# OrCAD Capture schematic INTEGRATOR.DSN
size A; title: Integrator; rev: A; company: EMA Design Automation; note: EMA-12345678; note: 225 Tech Park Dr; note: Rochester, NY, 14623
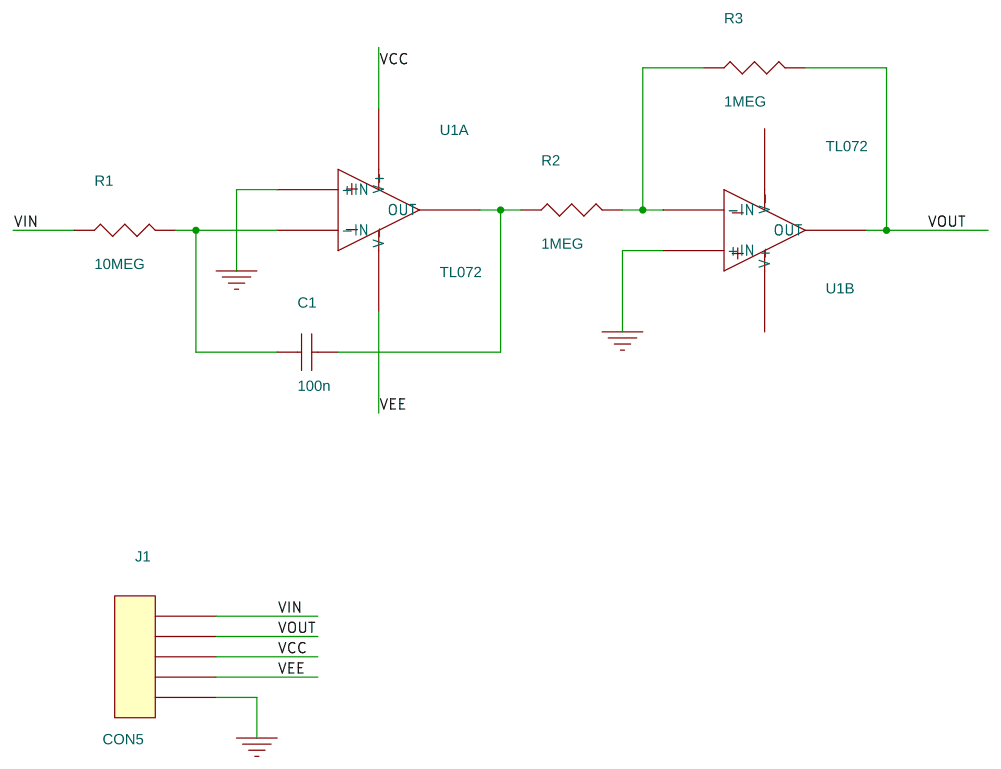
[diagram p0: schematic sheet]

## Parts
C1  100n
J1  CON5
R1  10MEG
R2  1MEG
R3  1MEG
U1  TL072  (sections A,B)

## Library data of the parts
C1 = CAP_NP
J1 = CON5
R1-R3 = RESISTOR
U1 = TL072_0

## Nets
GND: J1.5 U1.3(+IN) U1.5(+IN)
VCC: J1.3 U1.8(V+)
VEE: J1.4 U1.4(V-)
VIN: J1.1 R1.1
VOUT: J1.2 R3.2 U1.7(OUT)
N00229: C1.2 R2.1 U1.1(OUT)
N00233: R2.2 R3.1 U1.6(-IN)
N00241: C1.1 R1.2 U1.2(-IN)
